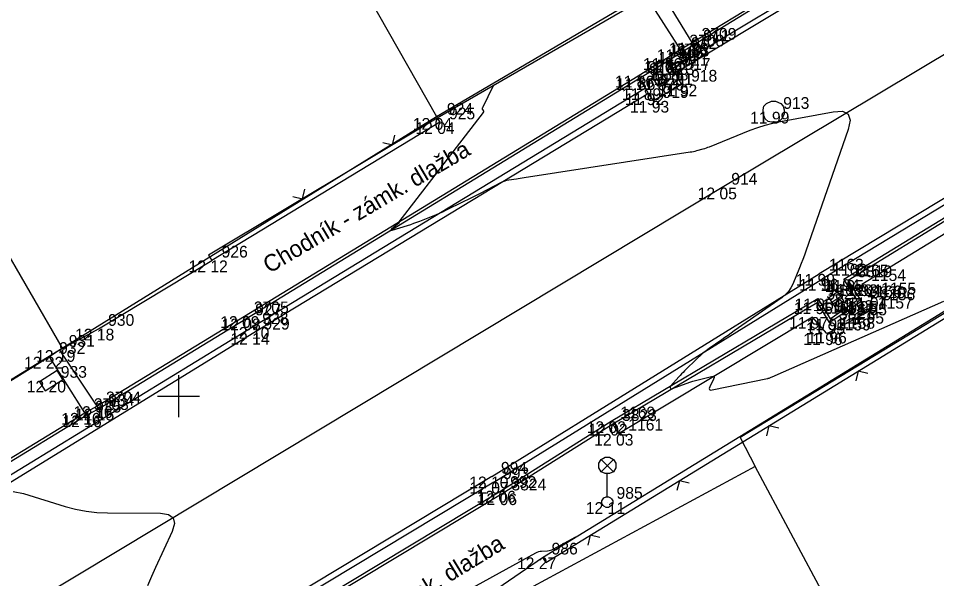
# Model space of a CAD drawing. Extents: x -703403 to -701924, y -1022520 to -1021856.
# Drawn here: x -703178.82 to -703156.9, y -1022104.36 to -1022090.98 of the extents above; entities that cross this region are included whole.
import ezdxf

# ---------------------------------------------------------------- set-up
doc = ezdxf.new("R2010")
doc.units = 0
for name, color, linetype in [('Ex_Major Contours', 7, 'Continuous'), ('Ex_Minor Contours', 7, 'Continuous'), ('Z_body', 7, 'Continuous'), ('Z_body_cisla', 7, 'Continuous'), ('Z_body_vysky_redukovane', 7, 'Continuous'), ('Z_budova', 7, 'Continuous'), ('Z_hektometricka_sit', 7, 'Continuous'), ('Z_katastr_hranice', 7, 'Continuous'), ('Z_katastr_vnitrni_kresba', 7, 'Continuous'), ('Z_komunikace', 7, 'Continuous'), ('Z_komunikace_osa', 7, 'Continuous'), ('Z_obruba', 7, 'Continuous'), ('Z_pilire', 7, 'Continuous'), ('Z_ploty', 7, 'Continuous'), ('Z_ploty_znacky', 7, 'Continuous'), ('Z_popisy', 7, 'Continuous'), ('Z_rozhranni', 7, 'Continuous'), ('Z_site_kanalizace_znaky', 7, 'Continuous'), ('Z_site_vo_znaky', 7, 'Continuous'), ('Z_vstupy', 7, 'Continuous'), ('Z_zlabek', 7, 'Continuous')]:
    doc.layers.add(name, color=color, linetype=linetype)

# ---------------------------------------------------------------- blocks, each defined once
blk = doc.blocks.new('POINT_DISPLAY')
blk.add_line((0, 0), (0, 0))
blk = doc.blocks.new('Z34')
for p, q in [((-0.2, 0.93), (-0.15, 1.02)), ((-0.2, 0.82), (-0.2, 0.93)), ((-0.15, 1.02), (-0.05, 1.07)), ((0.15, 0.72), (-0.15, 1.02)), ((0.15, 1.02), (-0.15, 0.72)), ((-0.05, 1.07), (0.05, 1.07)), ((0.05, 1.07), (0.15, 1.02)), ((0.15, 1.02), (0.2, 0.93)), ((0.2, 0.93), (0.2, 0.82)), ((-0.15, 0.72), (-0.2, 0.82)), ((-0.05, 0.68), (-0.15, 0.72)), ((0.05, 0.68), (-0.05, 0.68)), ((0, 0.13), (0, 0.68)), ((0.15, 0.72), (0.05, 0.68)), ((0.2, 0.82), (0.15, 0.72)), ((-0.13, 0.03), (-0.1, 0.08)), ((-0.13, -0.03), (-0.13, 0.03)), ((-0.1, 0.08), (-0.08, 0.1)), ((-0.08, 0.1), (-0.03, 0.13)), ((-0.03, 0.13), (0.03, 0.13)), ((0.03, 0.13), (0.08, 0.1)), ((0.08, 0.1), (0.1, 0.08)), ((0.1, 0.08), (0.13, 0.03)), ((0.13, 0.03), (0.13, -0.03)), ((-0.1, -0.08), (-0.13, -0.03)), ((-0.08, -0.1), (-0.1, -0.08)), ((-0.03, -0.13), (-0.08, -0.1)), ((0.03, -0.13), (-0.03, -0.13)), ((0.08, -0.1), (0.03, -0.13)), ((0.1, -0.08), (0.08, -0.1)), ((0.13, -0.03), (0.1, -0.08))]:
    blk.add_line(p, q)
blk = doc.blocks.new('Z666')
for p, q in [((-0.25, 0.13), (-0.25, -0.13)), ((0.25, 0.13), (-0.25, 0.13)), ((0.25, -0.13), (0.25, 0.13)), ((-0.25, -0.13), (0.25, -0.13))]:
    blk.add_line(p, q)
blk = doc.blocks.new('Z620')
for p, q in [((-0.17, 0.2), (-0.05, 0.25)), ((-0.05, 0.25), (0.05, 0.25)), ((0.05, 0.25), (0.17, 0.2)), ((-0.25, 0.05), (-0.23, 0.13)), ((-0.25, -0.05), (-0.25, 0.05)), ((-0.23, 0.13), (-0.17, 0.2)), ((0.17, 0.2), (0.23, 0.13)), ((0.23, 0.13), (0.25, 0.05)), ((0.25, 0.05), (0.25, -0.05)), ((-0.2, -0.17), (-0.25, -0.05)), ((-0.13, -0.23), (-0.2, -0.17)), ((0.2, -0.17), (0.13, -0.23)), ((0.25, -0.05), (0.2, -0.17)), ((-0.05, -0.25), (-0.13, -0.23)), ((0.05, -0.25), (-0.05, -0.25)), ((0.13, -0.23), (0.05, -0.25))]:
    blk.add_line(p, q)
blk = doc.blocks.new('Z46260')
for p, q in [((0.13, 0.13), (-0.13, 0.13)), ((-0.13, 0.13), (-0.13, -0.13)), ((0.13, 0), (-0.13, 0)), ((0.13, -0.13), (0.13, 0.13)), ((-0.13, -0.13), (0.13, -0.13))]:
    blk.add_line(p, q)
blk = doc.blocks.new('Z212')
for p, q in [((-0.17, 0.17), (0, 0)), ((0, 0), (0.17, 0.17))]:
    blk.add_line(p, q)

msp = doc.modelspace()

# ---------------------------------------------------------------- linework, layer by layer
at = {"layer": 'Ex_Major Contours'}
msp.add_lwpolyline([(-703167.487, -1022092.589), (-703167.743, -1022093.115), (-703167.747, -1022093.125), (-703167.748, -1022093.135), (-703167.746, -1022093.145), (-703167.742, -1022093.155), (-703167.718, -1022093.194), (-703167.714, -1022093.204), (-703167.713, -1022093.213), (-703167.715, -1022093.222), (-703167.721, -1022093.231), (-703169.738, -1022095.839), (-703169.739, -1022095.841), (-703169.74, -1022095.844), (-703169.74, -1022095.847), (-703169.739, -1022095.85), (-703169.733, -1022095.862), (-703169.732, -1022095.864), (-703169.732, -1022095.867), (-703169.733, -1022095.869), (-703169.735, -1022095.872), (-703169.911, -1022096.014), (-703169.933, -1022096.034), (-703169.938, -1022096.045), (-703169.926, -1022096.046), (-703169.898, -1022096.039), (-703169.528, -1022095.922), (-703169.454, -1022095.898), (-703169.381, -1022095.873), (-703169.308, -1022095.846), (-703169.235, -1022095.819), (-703168.917, -1022095.696), (-703168.841, -1022095.665), (-703168.765, -1022095.632), (-703168.69, -1022095.598), (-703168.615, -1022095.563), (-703168.176, -1022095.346), (-703168.078, -1022095.298), (-703167.98, -1022095.249), (-703167.883, -1022095.2), (-703167.786, -1022095.15), (-703167.287, -1022094.892), (-703167.246, -1022094.873), (-703167.203, -1022094.857), (-703167.159, -1022094.845), (-703167.114, -1022094.837), (-703166.931, -1022094.81), (-703166.886, -1022094.803), (-703166.84, -1022094.796), (-703166.794, -1022094.79), (-703166.749, -1022094.783), (-703162.783, -1022094.17), (-703162.743, -1022094.163), (-703162.704, -1022094.155), (-703162.665, -1022094.147), (-703162.626, -1022094.137), (-703162.471, -1022094.095), (-703162.432, -1022094.084), (-703162.394, -1022094.072), (-703162.356, -1022094.058), (-703162.319, -1022094.044), (-703161.345, -1022093.652), (-703161.168, -1022093.586), (-703160.99, -1022093.53), (-703160.809, -1022093.482), (-703160.625, -1022093.443), (-703159.367, -1022093.209), (-703159.141, -1022093.198), (-703159.005, -1022093.264), (-703158.96, -1022093.408), (-703159.005, -1022093.63), (-703160.017, -1022096.536), (-703160.053, -1022096.636), (-703160.09, -1022096.736), (-703160.128, -1022096.834), (-703160.168, -1022096.932), (-703160.33, -1022097.324), (-703160.376, -1022097.417), (-703160.434, -1022097.501), (-703160.503, -1022097.576), (-703160.584, -1022097.642), (-703161.728, -1022098.444), (-703161.803, -1022098.496), (-703161.877, -1022098.548), (-703161.952, -1022098.6), (-703162.026, -1022098.652), (-703162.327, -1022098.861), (-703162.4, -1022098.914), (-703162.47, -1022098.969), (-703162.537, -1022099.028), (-703162.603, -1022099.089), (-703162.915, -1022099.396), (-703162.951, -1022099.432), (-703162.986, -1022099.468), (-703163.02, -1022099.504), (-703163.055, -1022099.541), (-703163.254, -1022099.758), (-703163.256, -1022099.761), (-703163.258, -1022099.763), (-703163.259, -1022099.766), (-703163.26, -1022099.769), (-703163.263, -1022099.782), (-703163.263, -1022099.785), (-703163.263, -1022099.788), (-703163.262, -1022099.791), (-703163.261, -1022099.794), (-703163.243, -1022099.821), (-703163.239, -1022099.825), (-703163.234, -1022099.828), (-703163.229, -1022099.828), (-703163.224, -1022099.827), (-703162.85, -1022099.688), (-703162.786, -1022099.665), (-703162.721, -1022099.644), (-703162.655, -1022099.625), (-703162.589, -1022099.607), (-703162.275, -1022099.53), (-703162.234, -1022099.525), (-703162.211, -1022099.534), (-703162.207, -1022099.558), (-703162.221, -1022099.597), (-703162.314, -1022099.78), (-703162.328, -1022099.819), (-703162.323, -1022099.843), (-703162.301, -1022099.854), (-703162.259, -1022099.851), (-703160.937, -1022099.579), (-703160.927, -1022099.576), (-703160.918, -1022099.574), (-703160.908, -1022099.571), (-703160.899, -1022099.567), (-703160.862, -1022099.553), (-703160.844, -1022099.545), (-703160.826, -1022099.537), (-703156.725, -1022097.729)], dxfattribs=at)
at = {"layer": 'Ex_Minor Contours'}
for points in [[(-703178.948, -1022102.274), (-703178.702, -1022102.325), (-703177.709, -1022102.632), (-703177.459, -1022102.7), (-703177.206, -1022102.748), (-703176.951, -1022102.778), (-703176.692, -1022102.789), (-703175.43, -1022102.796), (-703175.235, -1022102.824), (-703175.123, -1022102.906), (-703175.096, -1022103.041), (-703175.153, -1022103.229), (-703175.547, -1022104.091), (-703175.643, -1022104.308), (-703175.736, -1022104.526)], [(-703168.591, -1022104.913), (-703166.464, -1022103.739), (-703166.432, -1022103.723), (-703166.399, -1022103.712), (-703166.365, -1022103.704), (-703166.33, -1022103.699), (-703166.188, -1022103.69), (-703166.152, -1022103.686), (-703166.118, -1022103.678), (-703166.085, -1022103.666), (-703166.053, -1022103.651), (-703165.515, -1022103.362)]]:
    msp.add_lwpolyline(points, dxfattribs=at)
at = {"layer": 'Z_budova'}
for p, q in [((-703163.82, -1022090.47), (-703168.82, -1022093.36)), ((-703178.08, -1022099.06), (-703182.45, -1022101.76)), ((-703177.84, -1022098.9), (-703178.08, -1022099.06))]:
    msp.add_line(p, q, dxfattribs=at)
at = {"layer": 'Z_hektometricka_sit'}
for p, q in [((-703175, -1022099.5), (-703175, -1022100.5)), ((-703175.5, -1022100), (-703174.5, -1022100))]:
    msp.add_line(p, q, dxfattribs=at)
at = {"layer": 'Z_katastr_hranice'}
for p, q in [((-703178.37, -1022076.52), (-703168.84, -1022093.32)), ((-703168.84, -1022093.32), (-703163.58, -1022090.23)), ((-703177.78, -1022098.85), (-703168.84, -1022093.32)), ((-703156.06, -1022097.62), (-703161.59, -1022100.99)), ((-703182.66, -1022101.86), (-703177.78, -1022098.85)), ((-703161.59, -1022100.99), (-703161.23, -1022101.68)), ((-703161.23, -1022101.68), (-703170.12, -1022106.48)), ((-703145.85, -1022130.32), (-703161.23, -1022101.68))]:
    msp.add_line(p, q, dxfattribs=at)
at = {"layer": 'Z_katastr_vnitrni_kresba'}
msp.add_line((-703186.45, -1022083.86), (-703177.78, -1022098.85), dxfattribs=at)
at = {"layer": 'Z_komunikace'}
for p, q in [((-703154.98, -1022087.38), (-703163.14, -1022092.29)), ((-703163.14, -1022092.29), (-703162.99, -1022092.56)), ((-703152.02, -1022092.43), (-703159.7, -1022097.08)), ((-703162.99, -1022092.56), (-703163.66, -1022092.95)), ((-703163.78, -1022092.77), (-703173.2, -1022098.49)), ((-703163.66, -1022092.95), (-703163.78, -1022092.77)), ((-703167.52, -1022101.92), (-703159.7, -1022097.08)), ((-703173.2, -1022098.49), (-703181.38, -1022103.51)), ((-703167.52, -1022101.92), (-703176.23, -1022107.16))]:
    msp.add_line(p, q, dxfattribs=at)
at = {"layer": 'Z_komunikace_osa'}
for p, q in [((-703153.71, -1022090.05), (-703162.02, -1022095.02)), ((-703162.02, -1022095.02), (-703180.13, -1022105.91))]:
    msp.add_line(p, q, dxfattribs=at)
at = {"layer": 'Z_obruba'}
for p, q in [((-703162.73, -1022091.56), (-703155.26, -1022086.96)), ((-703155.06, -1022087.25), (-703163.2, -1022092.18)), ((-703163.02, -1022091.72), (-703162.73, -1022091.56)), ((-703163.35, -1022091.93), (-703163.02, -1022091.72)), ((-703164.02, -1022092.35), (-703163.35, -1022091.93)), ((-703173.42, -1022098.09), (-703164.02, -1022092.35)), ((-703163.85, -1022092.65), (-703173.23, -1022098.35)), ((-703151.97, -1022092.55), (-703159.62, -1022097.2)), ((-703159.01, -1022097.23), (-703151.88, -1022092.84)), ((-703167.47, -1022102.05), (-703159.62, -1022097.2)), ((-703158.69, -1022097.73), (-703159.01, -1022097.23)), ((-703164.63, -1022100.66), (-703159.75, -1022097.76)), ((-703159.75, -1022097.76), (-703159.46, -1022098.24)), ((-703159.46, -1022098.24), (-703158.69, -1022097.73)), ((-703176.95, -1022100.24), (-703173.42, -1022098.09)), ((-703173.23, -1022098.35), (-703181.5, -1022103.41)), ((-703181.55, -1022103.03), (-703177.24, -1022100.4)), ((-703177.24, -1022100.4), (-703176.95, -1022100.24)), ((-703167.27, -1022102.32), (-703164.63, -1022100.66)), ((-703167.47, -1022102.05), (-703176.14, -1022107.27)), ((-703175.89, -1022107.51), (-703167.27, -1022102.32))]:
    msp.add_line(p, q, dxfattribs=at)
at = {"layer": 'Z_ploty'}
for p, q in [((-703168.82, -1022093.36), (-703174.28, -1022096.63)), ((-703168.82, -1022093.36), (-703168.76, -1022093.46)), ((-703168.76, -1022093.46), (-703174.2, -1022096.76)), ((-703174.28, -1022096.63), (-703174.2, -1022096.76)), ((-703166.31, -1022103.85), (-703155.97, -1022097.51)), ((-703166.23, -1022103.97), (-703155.89, -1022097.64)), ((-703166.31, -1022103.85), (-703166.23, -1022103.97))]:
    msp.add_line(p, q, dxfattribs=at)
at = {"layer": 'Z_rozhranni'}
for p, q in [((-703163.2, -1022092.18), (-703163.32, -1022092)), ((-703163.14, -1022092.29), (-703163.2, -1022092.18)), ((-703163.85, -1022092.65), (-703163.99, -1022092.41)), ((-703163.78, -1022092.77), (-703163.85, -1022092.65))]:
    msp.add_line(p, q, dxfattribs=at)
at = {"layer": 'Z_vstupy'}
for p, q in [((-703176.91, -1022098.39), (-703174.2, -1022096.76)), ((-703177.84, -1022098.9), (-703176.91, -1022098.39)), ((-703169.24, -1022105.86), (-703166.31, -1022103.85))]:
    msp.add_line(p, q, dxfattribs=at)
at = {"layer": 'Z_zlabek'}
for p, q in [((-703162.7, -1022091.61), (-703155.23, -1022087.02)), ((-703162.73, -1022091.56), (-703163.51, -1022090.28)), ((-703163.82, -1022090.47), (-703163.02, -1022091.72)), ((-703162.98, -1022091.78), (-703162.7, -1022091.61)), ((-703163.32, -1022092), (-703162.98, -1022091.78)), ((-703163.99, -1022092.41), (-703163.32, -1022092)), ((-703173.39, -1022098.15), (-703163.99, -1022092.41)), ((-703159.11, -1022097.21), (-703151.92, -1022092.79)), ((-703151.79, -1022093.11), (-703158.68, -1022097.33)), ((-703158.79, -1022097.71), (-703159.11, -1022097.21)), ((-703158.68, -1022097.33), (-703158.45, -1022097.64)), ((-703164.67, -1022100.6), (-703159.73, -1022097.67)), ((-703159.73, -1022097.67), (-703159.44, -1022098.15)), ((-703159.44, -1022098.15), (-703158.79, -1022097.71)), ((-703158.46, -1022097.79), (-703158.53, -1022097.99)), ((-703158.45, -1022097.64), (-703158.46, -1022097.79)), ((-703158.53, -1022097.99), (-703159.42, -1022098.46)), ((-703176.91, -1022100.3), (-703173.39, -1022098.15)), ((-703159.86, -1022098.11), (-703164.49, -1022100.9)), ((-703159.52, -1022098.5), (-703159.86, -1022098.11)), ((-703159.42, -1022098.46), (-703159.52, -1022098.5)), ((-703177.24, -1022100.4), (-703178.08, -1022099.06)), ((-703177.84, -1022098.9), (-703176.95, -1022100.24)), ((-703177.21, -1022100.46), (-703176.91, -1022100.3)), ((-703181.51, -1022103.09), (-703177.21, -1022100.46)), ((-703167.3, -1022102.26), (-703164.67, -1022100.6)), ((-703164.49, -1022100.9), (-703164.63, -1022100.66)), ((-703175.93, -1022107.45), (-703167.3, -1022102.26))]:
    msp.add_line(p, q, dxfattribs=at)

# ---------------------------------------------------------------- block references
at = {"layer": 'Z_body'}
for p in [(-703162.73, -1022091.56), (-703162.7, -1022091.61), (-703163.02, -1022091.72), (-703162.98, -1022091.78), (-703163.35, -1022091.93), (-703163.32, -1022092), (-703163.2, -1022092.18), (-703163.14, -1022092.29), (-703164.02, -1022092.35), (-703163.99, -1022092.41), (-703163.52, -1022092.41), (-703163.85, -1022092.65), (-703162.99, -1022092.56), (-703163.78, -1022092.77), (-703163.66, -1022092.95), (-703168.82, -1022093.36), (-703160.79, -1022093.21), (-703168.76, -1022093.46), (-703162.02, -1022095.02), (-703174.2, -1022096.76), (-703159.7, -1022097.08), (-703159.62, -1022097.2), (-703159.11, -1022097.21), (-703159.01, -1022097.23), (-703158.68, -1022097.33), (-703159.75, -1022097.76), (-703159.73, -1022097.67), (-703159.29, -1022097.69), (-703158.79, -1022097.71), (-703158.69, -1022097.73), (-703158.46, -1022097.79), (-703158.45, -1022097.64), (-703158.53, -1022097.99), (-703173.42, -1022098.09), (-703173.39, -1022098.15), (-703159.86, -1022098.11), (-703159.44, -1022098.15), (-703176.91, -1022098.39), (-703173.23, -1022098.35), (-703159.46, -1022098.24), (-703173.2, -1022098.49), (-703159.52, -1022098.5), (-703159.42, -1022098.46), (-703178.08, -1022099.06), (-703177.84, -1022098.9), (-703178.04, -1022099.63), (-703177.24, -1022100.4), (-703176.95, -1022100.24), (-703176.91, -1022100.3), (-703177.21, -1022100.46), (-703164.67, -1022100.6), (-703164.63, -1022100.66), (-703164.49, -1022100.9), (-703167.52, -1022101.92), (-703167.47, -1022102.05), (-703167.3, -1022102.26), (-703167.27, -1022102.32), (-703164.76, -1022102.53), (-703166.31, -1022103.85)]:
    msp.add_blockref('POINT_DISPLAY', p, dxfattribs=at)
at = {"layer": 'Z_pilire', "rotation": 32.4}
msp.add_blockref('Z666', (-703178.04, -1022099.63), dxfattribs=at)
at = {"layer": 'Z_ploty_znacky'}
for p, rotation in [((-703169.89, -1022094), 30.9), ((-703172.04, -1022095.29), 30.9), ((-703158.77, -1022099.4), -148.50000000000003), ((-703160.9, -1022100.71), -148.50000000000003), ((-703163.04, -1022102.02), -148.50000000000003), ((-703165.17, -1022103.32), -148.50000000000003)]:
    msp.add_blockref('Z212', p, dxfattribs=dict(at, rotation=rotation))
at = {"layer": 'Z_site_kanalizace_znaky'}
for p, rotation in [((-703163.52, -1022092.41), 32.4), ((-703159.29, -1022097.69), 34.199999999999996)]:
    msp.add_blockref('Z46260', p, dxfattribs=dict(at, rotation=rotation))
msp.add_blockref('Z620', (-703160.79, -1022093.21), dxfattribs=at)
at = {"layer": 'Z_site_vo_znaky'}
msp.add_blockref('Z34', (-703164.76, -1022102.53), dxfattribs=at)

# ---------------------------------------------------------------- texts
at = {"layer": 'Z_body_cisla'}
for s, p in [('3709', (-703162.51, -1022091.49)), ('3708', (-703162.8, -1022091.65)), ('912', (-703162.76, -1022091.71)), ('911', (-703162.47, -1022091.53)), ('3707', (-703163.13, -1022091.86)), ('915', (-703163.1, -1022091.93)), ('921', (-703162.97, -1022092.11)), ('3706', (-703163.8, -1022092.28)), ('916', (-703163.76, -1022092.33)), ('923', (-703163.3, -1022092.33)), ('917', (-703162.92, -1022092.21)), ('922', (-703163.63, -1022092.58)), ('918', (-703162.76, -1022092.49)), ('920', (-703163.55, -1022092.7)), ('919', (-703163.44, -1022092.88)), ('913', (-703160.56, -1022093.14)), ('924', (-703168.59, -1022093.28)), ('925', (-703168.54, -1022093.39)), ('914', (-703161.8, -1022094.95)), ('926', (-703173.97, -1022096.69)), ('1163', (-703159.47, -1022097)), ('1162', (-703159.39, -1022097.12)), ('1165', (-703158.88, -1022097.14)), ('3819', (-703158.79, -1022097.16)), ('1154', (-703158.46, -1022097.25)), ('1168', (-703159.5, -1022097.6)), ('1164', (-703159.06, -1022097.61)), ('1166', (-703158.56, -1022097.64)), ('1155', (-703158.22, -1022097.57)), ('3822', (-703159.53, -1022097.69)), ('3820', (-703158.47, -1022097.66)), ('1156', (-703158.24, -1022097.71)), ('3705', (-703173.2, -1022098.02)), ('927', (-703173.17, -1022098.07)), ('1160', (-703159.63, -1022098.03)), ('1167', (-703159.21, -1022098.07)), ('1157', (-703158.3, -1022097.91)), ('928', (-703173, -1022098.28)), ('3821', (-703159.23, -1022098.17)), ('930', (-703176.68, -1022098.32)), ('929', (-703172.97, -1022098.41)), ('1159', (-703159.3, -1022098.43)), ('1158', (-703159.2, -1022098.39)), ('931', (-703177.62, -1022098.82)), ('932', (-703177.85, -1022098.99)), ('933', (-703177.81, -1022099.56)), ('3704', (-703176.73, -1022100.17)), ('934', (-703176.68, -1022100.23)), ('3703', (-703177.02, -1022100.33)), ('935', (-703176.99, -1022100.39)), ('1169', (-703164.45, -1022100.53)), ('3823', (-703164.41, -1022100.59)), ('1161', (-703164.26, -1022100.82)), ('994', (-703167.3, -1022101.85)), ('993', (-703167.25, -1022101.98)), ('992', (-703167.08, -1022102.19)), ('3824', (-703167.05, -1022102.25)), ('985', (-703164.54, -1022102.45)), ('986', (-703166.09, -1022103.78))]:
    msp.add_text(s, height=0.28, dxfattribs=at).set_placement(p)
at = {"layer": 'Z_body_vysky_redukovane'}
for s, p in [('11 86', (-703163.29, -1022091.84)), ('11 83', (-703163.26, -1022091.89)), ('11 86', (-703163.58, -1022092)), ('11 84', (-703163.54, -1022092.06)), ('11 86', (-703163.91, -1022092.21)), ('11 84', (-703163.88, -1022092.28)), ('11 88', (-703163.76, -1022092.46)), ('11 91', (-703163.653, -1022092.57)), ('11 86', (-703164.58, -1022092.63)), ('11 86', (-703164.55, -1022092.69)), ('11 87', (-703164.08, -1022092.69)), ('11 89', (-703164.41, -1022092.93)), ('11 92', (-703163.55, -1022092.84)), ('11 92', (-703164.34, -1022093.05)), ('11 93', (-703164.22, -1022093.23)), ('12 04', (-703169.403, -1022093.64)), ('11 99', (-703161.35, -1022093.49)), ('12 04', (-703169.343, -1022093.74)), ('12 05', (-703162.603, -1022095.3)), ('12 12', (-703174.76, -1022097.04)), ('11 99', (-703160.26, -1022097.36)), ('11 96', (-703160.18, -1022097.48)), ('11 94', (-703159.67, -1022097.49)), ('11 95', (-703159.57, -1022097.51)), ('11 93', (-703159.24, -1022097.61)), ('11 95', (-703160.31, -1022098.04)), ('11 95', (-703160.29, -1022097.95)), ('11 92', (-703159.85, -1022097.97)), ('11 93', (-703159.35, -1022097.99)), ('11 95', (-703159.25, -1022098.01)), ('11 95', (-703159.02, -1022098.07)), ('11 94', (-703159.01, -1022097.92)), ('11 95', (-703159.09, -1022098.27)), ('12 09', (-703174.003, -1022098.37)), ('12 08', (-703173.973, -1022098.43)), ('11 97', (-703160.42, -1022098.39)), ('11 93', (-703160, -1022098.43)), ('12 18', (-703177.47, -1022098.67)), ('12 10', (-703173.767, -1022098.63)), ('11 95', (-703160.02, -1022098.52)), ('12 14', (-703173.76, -1022098.77)), ('11 96', (-703160.08, -1022098.78)), ('11 96', (-703159.98, -1022098.74)), ('12 22', (-703178.687, -1022099.34)), ('12 19', (-703178.4, -1022099.18)), ('12 20', (-703178.623, -1022099.91)), ('12 16', (-703177.8, -1022100.68)), ('12 16', (-703177.51, -1022100.52)), ('12 15', (-703177.47, -1022100.58)), ('12 16', (-703177.77, -1022100.74)), ('12 02', (-703165.253, -1022100.88)), ('12 02', (-703165.213, -1022100.94)), ('12 03', (-703165.073, -1022101.18)), ('12 10', (-703168.057, -1022102.2)), ('12 07', (-703168.053, -1022102.33)), ('12 06', (-703167.883, -1022102.54)), ('12 06', (-703167.853, -1022102.6)), ('12 11', (-703165.273, -1022102.81)), ('12 27', (-703166.917, -1022104.13))]:
    msp.add_text(s, height=0.28, dxfattribs=at).set_placement(p)
at = {"layer": 'Z_popisy'}
for rotation, p in [(30.6, (-703172.83, -1022097.08)), (31.5, (-703171.97, -1022106.56))]:
    msp.add_text('Chodník - zámk. dlažba', height=0.4, rotation=rotation, dxfattribs=at).set_placement(p)

doc.saveas('drawing.dxf')
